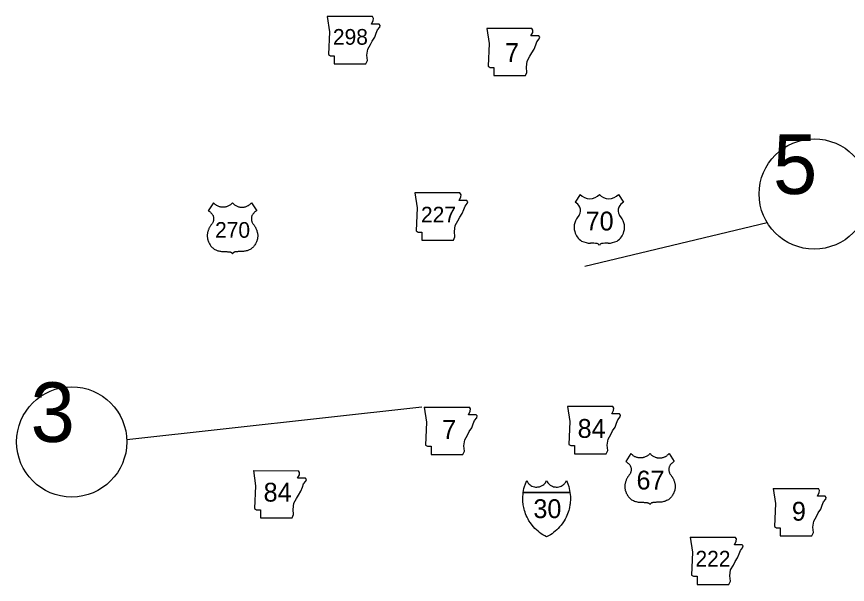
# Model space of a CAD drawing. Extents: x -819161 to 80911, y -6604 to 768454.
# Drawn here: x 40617 to 43414, y -6191 to -4281 of the extents above; entities that cross this region are included whole.
import ezdxf

# ---------------------------------------------------------------- set-up
doc = ezdxf.new("R2010")
doc.units = 0
for name, color, linetype in [('23', 7, 'Continuous'), ('DSN_DRFT_Common-Line', 7, 'Continuous'), ('Level 21', 7, 'Continuous'), ('Level 22', 7, 'Continuous'), ('Level 23', 7, 'Continuous')]:
    doc.layers.add(name, color=color, linetype=linetype)

msp = doc.modelspace()

# ---------------------------------------------------------------- linework, layer by layer
at = {"layer": '23'}
for points in [[(42322.5, -5882.3), (42323.6, -5875), (42325.1, -5868.2), (42326.9, -5861.5), (42329.7, -5853), (42334.3, -5841.8), (42337.8, -5847.7), (42339.4, -5850.2), (42341, -5852.2), (42342.9, -5854), (42345.7, -5856.4), (42348.6, -5858.5), (42351.8, -5860.3), (42355.9, -5861.9), (42360, -5862.8), (42364.3, -5863.4), (42368.9, -5863.6), (42372.2, -5863.3), (42374.9, -5863), (42377.8, -5862.3), (42381.8, -5860.8), (42384.5, -5859.7), (42386.7, -5858.5), (42388.9, -5857.1), (42391.4, -5855.1), (42394.8, -5851.8), (42397.1, -5848.9), (42399.1, -5845.7), (42401.3, -5842)], [(42401.3, -5842), (42403.4, -5845.7), (42405.4, -5848.9), (42407.8, -5851.8), (42411.1, -5855.1), (42413.7, -5857.1), (42415.8, -5858.5), (42418.1, -5859.7), (42420.7, -5860.8), (42424.8, -5862.3), (42427.7, -5863), (42430.4, -5863.3), (42433.7, -5863.6), (42438.3, -5863.4), (42442.6, -5862.8), (42446.6, -5861.9), (42450.7, -5860.3), (42453.9, -5858.5), (42456.8, -5856.4), (42459.6, -5854), (42461.6, -5852.2), (42463.2, -5850.2), (42464.7, -5847.7), (42468.3, -5841.8), (42472.9, -5853), (42475.6, -5861.5), (42477.5, -5868.2), (42478.9, -5875), (42480, -5882.3)], [(42401.3, -6031.3), (42395, -6028), (42388.5, -6024.1), (42382.9, -6020.4), (42377.9, -6016.7), (42372.6, -6012.4), (42366.8, -6007.3), (42362.1, -6002.6), (42357.7, -5997.9), (42352.8, -5992.1), (42346.8, -5984.1), (42342, -5976.7), (42338.9, -5971.3), (42335.9, -5965.4), (42332.8, -5958.8), (42330.5, -5953.1), (42328.6, -5947.8), (42327, -5942.6), (42325.6, -5937.5), (42324.2, -5931.9), (42322.8, -5923.9), (42322.2, -5919.7), (42321.6, -5914), (42321.3, -5907.4), (42321.2, -5901.7), (42321.4, -5895.5), (42321.9, -5888.8), (42322.6, -5882.3)], [(42322.5, -5882.3), (42480, -5882.3)], [(42480, -5882.3), (42322.5, -5882.3)], [(42479.9, -5882.3), (42480.7, -5888.8), (42481.2, -5895.5), (42481.3, -5901.7), (42481.3, -5907.4), (42480.9, -5914), (42480.4, -5919.7), (42479.8, -5923.9), (42478.3, -5931.9), (42477, -5937.5), (42475.6, -5942.6), (42473.9, -5947.8), (42472, -5953.1), (42469.7, -5958.8), (42466.7, -5965.4), (42463.6, -5971.3), (42460.5, -5976.7), (42455.7, -5984.1), (42449.8, -5992.1), (42444.8, -5997.9), (42440.5, -6002.6), (42435.7, -6007.3), (42430, -6012.4), (42424.7, -6016.7), (42419.6, -6020.4), (42414.1, -6024.1), (42407.5, -6028), (42401.3, -6031.3)]]:
    msp.add_lwpolyline(points, dxfattribs=at)
at = {"layer": 'DSN_DRFT_Common-Line'}
msp.add_line((43144.1, -4973.9), (42530, -5121.1), dxfattribs=at)
msp.add_lwpolyline([(40987.4, -5703.1), (41981.2, -5593.9)], dxfattribs=at)
for centre in [(43302.5, -4877.4), (40802.1, -5711.7)]:
    msp.add_circle(centre, 185.5, dxfattribs=at)
at = {"layer": 'Level 21'}
for p, q in [((41989.4, -5594.6), (41997, -5645.3)), ((42145.1, -5600.5), (42141.6, -5594.7)), ((42138.3, -5620), (42144.2, -5608.1)), ((42164.5, -5620), (42138.3, -5620)), ((42144.2, -5608.1), (42145.1, -5600.5)), ((42167.9, -5624.2), (42164.5, -5620)), ((41997, -5645.3), (41993.7, -5722.3)), ((42149.3, -5664), (42154.4, -5650.4)), ((42154.4, -5650.4), (42158.6, -5639.4)), ((42158.6, -5639.4), (42166.2, -5630.1)), ((42166.2, -5630.1), (42167.9, -5624.2)), ((42134.9, -5688.5), (42140.8, -5676.6)), ((42140.8, -5676.6), (42149.3, -5664)), ((42123.1, -5724.9), (42125.6, -5704.6)), ((42125.6, -5704.6), (42134.9, -5688.5)), ((41993.7, -5722.3), (42000.4, -5726.5)), ((42000.4, -5726.5), (42013.1, -5726.5)), ((42013.1, -5726.5), (42013.1, -5753.6)), ((42124.8, -5742.6), (42123.1, -5724.9)), ((42013.1, -5753.6), (42119.7, -5753.6)), ((42119.7, -5753.6), (42124.8, -5742.6)), ((41413.9, -5808.3), (41421.5, -5859.1)), ((41569.6, -5814.2), (41566.1, -5808.4)), ((41568.7, -5821.9), (41569.6, -5814.2)), ((41562.8, -5833.7), (41568.7, -5821.9)), ((41589, -5833.7), (41562.8, -5833.7)), ((41583.1, -5853.2), (41590.7, -5843.9)), ((41592.4, -5837.9), (41589, -5833.7)), ((41590.7, -5843.9), (41592.4, -5837.9)), ((41421.5, -5859.1), (41418.2, -5936.1)), ((41573.8, -5877.7), (41578.9, -5864.2)), ((41578.9, -5864.2), (41583.1, -5853.2)), ((43164.6, -5868.7), (43172.2, -5919.4)), ((43320.2, -5874.6), (43316.7, -5868.7)), ((43319.4, -5882.2), (43320.2, -5874.6)), ((41550.1, -5918.3), (41559.4, -5902.2)), ((41559.4, -5902.2), (41565.3, -5890.4)), ((41565.3, -5890.4), (41573.8, -5877.7)), ((43313.5, -5894.1), (43319.4, -5882.2)), ((43339.7, -5894.1), (43313.5, -5894.1)), ((43343.1, -5898.3), (43339.7, -5894.1)), ((43341.4, -5904.2), (43343.1, -5898.3)), ((41547.6, -5938.6), (41550.1, -5918.3)), ((43172.2, -5919.4), (43168.8, -5996.4)), ((43324.5, -5938), (43329.5, -5924.5)), ((43329.5, -5924.5), (43333.8, -5913.5)), ((43333.8, -5913.5), (43341.4, -5904.2)), ((41418.2, -5936.1), (41424.9, -5940.3)), ((41424.9, -5940.3), (41437.6, -5940.3)), ((41437.6, -5940.3), (41437.6, -5967.4)), ((41544.2, -5967.4), (41549.3, -5956.4)), ((41549.3, -5956.4), (41547.6, -5938.6)), ((43310.1, -5962.6), (43316, -5950.7)), ((43316, -5950.7), (43324.5, -5938)), ((41437.6, -5967.4), (41544.2, -5967.4)), ((43298.2, -5998.9), (43300.8, -5978.6)), ((43300.8, -5978.6), (43310.1, -5962.6)), ((43168.8, -5996.4), (43175.6, -6000.6)), ((43175.6, -6000.6), (43188.3, -6000.6)), ((43188.3, -6000.6), (43188.3, -6027.7)), ((43299.9, -6016.7), (43298.2, -5998.9)), ((42884.6, -6032), (42892.2, -6082.7)), ((43040.3, -6037.9), (43036.8, -6032.1)), ((43039.4, -6045.5), (43040.3, -6037.9)), ((43188.3, -6027.7), (43294.9, -6027.7)), ((43294.9, -6027.7), (43299.9, -6016.7)), ((43033.5, -6057.4), (43039.4, -6045.5)), ((43059.7, -6057.4), (43033.5, -6057.4)), ((43053.8, -6076.8), (43061.4, -6067.5)), ((43063.1, -6061.6), (43059.7, -6057.4)), ((43061.4, -6067.5), (43063.1, -6061.6)), ((42892.2, -6082.7), (42888.9, -6159.7)), ((43044.5, -6101.3), (43049.6, -6087.8)), ((43049.6, -6087.8), (43053.8, -6076.8)), ((43020.8, -6141.9), (43030.1, -6125.9)), ((43030.1, -6125.9), (43036, -6114)), ((43036, -6114), (43044.5, -6101.3)), ((43018.3, -6162.2), (43020.8, -6141.9)), ((42888.9, -6159.7), (42895.6, -6163.9)), ((42895.6, -6163.9), (42908.3, -6163.9)), ((42908.3, -6163.9), (42908.3, -6191)), ((43014.9, -6191), (43020, -6180)), ((43020, -6180), (43018.3, -6162.2)), ((42908.3, -6191), (43014.9, -6191))]:
    msp.add_line(p, q, dxfattribs=at)
for points in [[(41662.6, -4280.6), (41670.2, -4331.3), (41666.8, -4408.3), (41673.6, -4412.5), (41686.3, -4412.5), (41686.3, -4439.6), (41792.9, -4439.6), (41798, -4428.6), (41796.3, -4410.8), (41798.8, -4390.5), (41808.1, -4374.5), (41814, -4362.6), (41822.5, -4349.9), (41827.6, -4336.4), (41831.8, -4325.4), (41839.4, -4316.1), (41841.1, -4310.2), (41837.7, -4305.9), (41811.5, -4305.9), (41817.4, -4294.1), (41818.3, -4286.5), (41814.7, -4280.6)], [(42199.7, -4320.1), (42207.4, -4370.8), (42204, -4447.8), (42210.7, -4452.1), (42223.4, -4452.1), (42223.4, -4479.1), (42330, -4479.1), (42335.1, -4468.1), (42333.4, -4450.4), (42335.9, -4430.1), (42345.2, -4414), (42351.2, -4402.1), (42359.6, -4389.5), (42364.7, -4375.9), (42368.9, -4364.9), (42376.5, -4355.6), (42378.2, -4349.7), (42374.8, -4345.5), (42348.6, -4345.5), (42354.5, -4333.6), (42355.4, -4326), (42351.9, -4320.2)], [(41957.4, -4873.8), (41965, -4924.5), (41961.6, -5001.5), (41968.4, -5005.7), (41981.1, -5005.7), (41981.1, -5032.8), (42087.7, -5032.8), (42092.8, -5021.8), (42091.1, -5004), (42093.6, -4983.7), (42102.9, -4967.7), (42108.8, -4955.8), (42117.3, -4943.1), (42122.4, -4929.6), (42126.6, -4918.6), (42134.2, -4909.3), (42135.9, -4903.4), (42132.5, -4899.2), (42106.3, -4899.2), (42112.2, -4887.3), (42113.1, -4879.7), (42109.6, -4873.9)], [(42471.9, -5592.3), (42479.5, -5643), (42476.1, -5720), (42482.9, -5724.2), (42495.6, -5724.2), (42495.6, -5751.3), (42602.1, -5751.3), (42607.2, -5740.3), (42605.5, -5722.5), (42608.1, -5702.2), (42617.4, -5686.2), (42623.3, -5674.3), (42631.7, -5661.6), (42636.8, -5648.1), (42641.1, -5637.1), (42648.7, -5627.8), (42650.4, -5621.9), (42647, -5617.6), (42620.8, -5617.6), (42626.7, -5605.8), (42627.5, -5598.2), (42624, -5592.3)]]:
    msp.add_lwpolyline(points, close=True, dxfattribs=at)
for points in [[(41989.4, -5594.6), (42141.6, -5594.7)], [(41413.9, -5808.3), (41566.1, -5808.4)], [(43164.6, -5868.7), (43316.7, -5868.7)], [(42884.6, -6032), (43036.8, -6032.1)]]:
    msp.add_lwpolyline(points, dxfattribs=at)
at = {"layer": 'Level 22'}
for p, q in [((42514.5, -4878.6), (42497.2, -4905.4)), ((42643.2, -4878.6), (42660.5, -4905.4))]:
    msp.add_line(p, q, dxfattribs=at)
for points in [[(41343.5, -4907.1), (41342.2, -4908.6), (41340.9, -4909.8), (41339.5, -4911.2), (41338, -4912.5), (41336.5, -4913.7), (41334.7, -4914.9), (41332.7, -4916.1), (41330.5, -4917.3), (41327.7, -4918.6), (41325.6, -4919.5), (41323.1, -4920.3), (41320.9, -4920.8), (41318.9, -4921.3), (41316.7, -4921.6), (41314.7, -4921.8), (41312, -4921.9), (41309.8, -4921.9), (41307.9, -4921.8), (41306, -4921.6), (41304.2, -4921.3), (41301.8, -4920.8), (41299.7, -4920.3), (41297.1, -4919.4), (41294.8, -4918.5), (41292.8, -4917.6), (41290.9, -4916.6), (41289.2, -4915.6), (41287.3, -4914.4), (41285.6, -4913.1), (41284.1, -4911.9), (41282.8, -4910.7), (41281.5, -4909.5), (41280.2, -4908.1), (41279.2, -4906.9), (41261.9, -4933.7), (41263.1, -4934.4), (41264.6, -4935.4), (41266, -4936.4), (41267.8, -4937.8), (41269.3, -4939.1), (41270.6, -4940.4), (41272, -4941.7), (41273.3, -4943.2), (41274.3, -4944.4), (41275.3, -4945.7), (41276.3, -4947.1), (41277.2, -4948.5), (41278.1, -4950.2), (41278.8, -4952.3), (41279.3, -4954.4), (41279.7, -4956.6), (41279.9, -4958.6), (41280, -4960.6), (41279.9, -4962.5), (41279.8, -4963.9), (41279.5, -4965.8), (41279.2, -4967.5), (41278.7, -4969.3), (41278.2, -4971), (41277.5, -4972.8), (41276.4, -4975.2), (41275.2, -4977), (41273.8, -4978.7), (41272.1, -4980.9), (41270.8, -4982.8), (41269.5, -4984.7), (41268.3, -4986.5), (41267.3, -4988.2), (41266.4, -4989.8), (41265.5, -4991.7), (41264.4, -4993.8), (41263.5, -4996), (41262.8, -4997.6), (41262.1, -4999.6), (41261.2, -5002.1), (41260.5, -5004.2), (41259.9, -5006.4), (41259.3, -5009.1), (41258.9, -5011.4), (41258.7, -5013.8), (41258.5, -5016.5), (41258.5, -5019), (41258.6, -5021.4), (41258.9, -5024.3), (41259.4, -5027), (41259.8, -5029.1), (41260.3, -5030.9), (41260.9, -5032.9), (41261.7, -5035.5), (41262.8, -5038.6), (41263.8, -5040.8), (41264.9, -5043.2), (41266.2, -5045.5), (41267.8, -5048.1), (41269.5, -5050.5), (41271.1, -5052.6), (41273, -5054.8), (41275.4, -5057.2), (41277.4, -5059.1), (41279.5, -5060.9)], [(41343.5, -4907.1), (41344.8, -4908.6), (41346.1, -4909.8), (41347.5, -4911.2), (41349.1, -4912.5), (41350.5, -4913.7), (41352.4, -4914.9), (41354.3, -4916.1), (41356.5, -4917.3), (41359.3, -4918.6), (41361.4, -4919.5), (41363.9, -4920.3), (41366.1, -4920.8), (41368.1, -4921.3), (41370.3, -4921.6), (41372.3, -4921.8), (41375, -4921.9), (41377.2, -4921.9), (41379.2, -4921.8), (41381, -4921.6), (41382.8, -4921.3), (41385.2, -4920.8), (41387.3, -4920.3), (41390, -4919.4), (41392.2, -4918.5), (41394.2, -4917.6), (41396.1, -4916.6), (41397.8, -4915.6), (41399.7, -4914.4), (41401.5, -4913.1), (41403, -4911.9), (41404.2, -4910.7), (41405.5, -4909.5), (41406.8, -4908.1), (41407.9, -4906.9), (41425.2, -4933.7), (41423.9, -4934.4), (41422.5, -4935.4), (41421.1, -4936.4), (41419.2, -4937.8), (41417.7, -4939.1), (41416.4, -4940.4), (41415.1, -4941.7), (41413.7, -4943.2), (41412.7, -4944.4), (41411.7, -4945.7), (41410.7, -4947.1), (41409.8, -4948.5), (41408.9, -4950.2), (41408.2, -4952.3), (41407.7, -4954.4), (41407.3, -4956.6), (41407.1, -4958.6), (41407.1, -4960.6), (41407.1, -4962.5), (41407.2, -4963.9), (41407.5, -4965.8), (41407.8, -4967.5), (41408.3, -4969.3), (41408.8, -4971), (41409.5, -4972.8), (41410.7, -4975.2), (41411.8, -4977), (41413.2, -4978.7), (41414.9, -4980.9), (41416.3, -4982.8), (41417.6, -4984.7), (41418.7, -4986.5), (41419.7, -4988.2), (41420.6, -4989.8), (41421.6, -4991.7), (41422.6, -4993.8), (41423.6, -4996), (41424.2, -4997.6), (41425, -4999.6), (41425.8, -5002.1), (41426.5, -5004.2), (41427.1, -5006.4), (41427.7, -5009.1), (41428.1, -5011.4), (41428.4, -5013.8), (41428.5, -5016.5), (41428.5, -5019), (41428.4, -5021.4), (41428.1, -5024.3), (41427.7, -5027), (41427.2, -5029.1), (41426.7, -5030.9), (41426.2, -5032.9), (41425.4, -5035.5), (41424.2, -5038.6), (41423.2, -5040.8), (41422.1, -5043.2), (41420.8, -5045.5), (41419.2, -5048.1), (41417.5, -5050.5), (41415.9, -5052.6), (41414, -5054.8), (41411.6, -5057.2), (41409.6, -5059.1), (41407.5, -5060.9)], [(41279.5, -5060.9), (41281.7, -5062.5), (41284.3, -5064.2), (41287.6, -5065.7), (41291.4, -5067.2), (41294.5, -5068.2), (41297.3, -5069), (41300.5, -5069.7), (41303.5, -5070.2), (41306.7, -5070.7), (41310.8, -5071), (41313.9, -5071.1), (41316.5, -5071.1), (41319.1, -5071.2), (41321.7, -5071.2), (41324.1, -5071.4), (41326.2, -5071.5), (41328.3, -5071.7), (41331, -5072), (41333.7, -5072.3), (41335.2, -5072.5), (41336.5, -5072.8), (41338.1, -5073.4), (41339, -5073.9), (41339.8, -5074.4), (41340.9, -5075.3), (41341.9, -5076.3), (41342.7, -5077.4), (41343.5, -5078.7)], [(41407.5, -5060.9), (41405.4, -5062.5), (41402.7, -5064.2), (41399.5, -5065.7), (41395.6, -5067.2), (41392.5, -5068.2), (41389.7, -5069), (41386.5, -5069.7), (41383.5, -5070.2), (41380.3, -5070.7), (41376.3, -5071), (41373.2, -5071.1), (41370.5, -5071.1), (41367.9, -5071.2), (41365.4, -5071.2), (41362.9, -5071.4), (41360.8, -5071.5), (41358.7, -5071.7), (41356, -5072), (41353.4, -5072.3), (41351.8, -5072.5), (41350.5, -5072.8), (41348.9, -5073.4), (41348, -5073.9), (41347.2, -5074.4), (41346.1, -5075.3), (41345.1, -5076.3), (41344.3, -5077.4), (41343.5, -5078.7)], [(42749.4, -5750.7), (42748.1, -5752.2), (42746.9, -5753.5), (42745.4, -5754.8), (42743.9, -5756.2), (42742.4, -5757.3), (42740.6, -5758.6), (42738.7, -5759.8), (42736.5, -5761), (42733.7, -5762.3), (42731.5, -5763.1), (42729.1, -5763.9), (42726.9, -5764.5), (42724.8, -5764.9), (42722.6, -5765.3), (42720.7, -5765.5), (42717.9, -5765.6), (42715.7, -5765.6), (42713.8, -5765.4), (42712, -5765.3), (42710.1, -5765), (42707.8, -5764.5), (42705.6, -5763.9), (42703, -5763.1), (42700.8, -5762.2), (42698.7, -5761.3), (42696.9, -5760.3), (42695.2, -5759.3), (42693.2, -5758), (42691.5, -5756.7), (42690, -5755.5), (42688.7, -5754.4), (42687.4, -5753.1), (42686.1, -5751.8), (42685.1, -5750.6), (42667.8, -5777.4), (42669, -5778.1), (42670.5, -5779.1), (42671.9, -5780), (42673.7, -5781.5), (42675.2, -5782.8), (42676.6, -5784), (42677.9, -5785.4), (42679.3, -5786.9), (42680.2, -5788.1), (42681.2, -5789.3), (42682.2, -5790.7), (42683.2, -5792.2), (42684.1, -5793.9), (42684.7, -5795.9), (42685.2, -5798), (42685.6, -5800.2), (42685.8, -5802.3), (42685.9, -5804.3), (42685.8, -5806.1), (42685.7, -5807.6), (42685.5, -5809.4), (42685.1, -5811.1), (42684.7, -5813), (42684.1, -5814.6), (42683.4, -5816.4), (42682.3, -5818.8), (42681.1, -5820.7), (42679.7, -5822.3), (42678.1, -5824.5), (42676.7, -5826.4), (42675.4, -5828.3), (42674.2, -5830.2), (42673.2, -5831.9), (42672.4, -5833.4), (42671.4, -5835.3), (42670.3, -5837.5), (42669.4, -5839.6), (42668.8, -5841.2), (42668, -5843.3), (42667.1, -5845.7), (42666.5, -5847.8), (42665.8, -5850.1), (42665.3, -5852.7), (42664.9, -5855), (42664.6, -5857.5), (42664.4, -5860.2), (42664.4, -5862.6), (42664.5, -5865.1), (42664.8, -5868), (42665.3, -5870.7), (42665.7, -5872.8), (42666.2, -5874.6), (42666.8, -5876.6), (42667.6, -5879.1), (42668.7, -5882.2), (42669.7, -5884.5), (42670.9, -5886.8), (42672.1, -5889.1), (42673.7, -5891.7), (42675.4, -5894.2), (42677.1, -5896.3), (42678.9, -5898.4), (42681.3, -5900.9), (42683.3, -5902.8), (42685.4, -5904.5)], [(42749.4, -5750.7), (42750.8, -5752.2), (42752, -5753.5), (42753.4, -5754.8), (42755, -5756.2), (42756.5, -5757.3), (42758.3, -5758.6), (42760.2, -5759.8), (42762.4, -5761), (42765.2, -5762.3), (42767.4, -5763.1), (42769.8, -5763.9), (42772, -5764.5), (42774.1, -5764.9), (42776.2, -5765.3), (42778.2, -5765.5), (42780.9, -5765.6), (42783.2, -5765.6), (42785.1, -5765.4), (42786.9, -5765.3), (42788.8, -5765), (42791.1, -5764.5), (42793.3, -5763.9), (42795.9, -5763.1), (42798.1, -5762.2), (42800.1, -5761.3), (42802, -5760.3), (42803.7, -5759.3), (42805.6, -5758), (42807.4, -5756.7), (42808.9, -5755.5), (42810.2, -5754.4), (42811.5, -5753.1), (42812.8, -5751.8), (42813.8, -5750.6), (42831.1, -5777.4), (42829.9, -5778.1), (42828.4, -5779.1), (42827, -5780), (42825.1, -5781.5), (42823.6, -5782.8), (42822.3, -5784), (42821, -5785.4), (42819.6, -5786.9), (42818.6, -5788.1), (42817.7, -5789.3), (42816.7, -5790.7), (42815.7, -5792.2), (42814.8, -5793.9), (42814.2, -5795.9), (42813.6, -5798), (42813.3, -5800.2), (42813.1, -5802.3), (42813, -5804.3), (42813, -5806.1), (42813.2, -5807.6), (42813.4, -5809.4), (42813.7, -5811.1), (42814.2, -5813), (42814.7, -5814.6), (42815.5, -5816.4), (42816.6, -5818.8), (42817.7, -5820.7), (42819.1, -5822.3), (42820.8, -5824.5), (42822.2, -5826.4), (42823.5, -5828.3), (42824.7, -5830.2), (42825.6, -5831.9), (42826.5, -5833.4), (42827.5, -5835.3), (42828.5, -5837.5), (42829.5, -5839.6), (42830.1, -5841.2), (42830.9, -5843.3), (42831.7, -5845.7), (42832.4, -5847.8), (42833, -5850.1), (42833.6, -5852.7), (42834, -5855), (42834.3, -5857.5), (42834.4, -5860.2), (42834.5, -5862.6), (42834.3, -5865.1), (42834, -5868), (42833.6, -5870.7), (42833.1, -5872.8), (42832.7, -5874.6), (42832.1, -5876.6), (42831.3, -5879.1), (42830.1, -5882.2), (42829.2, -5884.5), (42828, -5886.8), (42826.8, -5889.1), (42825.1, -5891.7), (42823.5, -5894.2), (42821.8, -5896.3), (42820, -5898.4), (42817.6, -5900.9), (42815.5, -5902.8), (42813.5, -5904.5)], [(42685.4, -5904.5), (42687.6, -5906.2), (42690.2, -5907.9), (42693.5, -5909.3), (42697.3, -5910.8), (42700.4, -5911.8), (42703.3, -5912.6), (42706.4, -5913.3), (42709.4, -5913.9), (42712.6, -5914.3), (42716.7, -5914.7), (42719.8, -5914.8), (42722.4, -5914.8), (42725, -5914.8), (42727.6, -5914.9), (42730, -5915), (42732.2, -5915.2), (42734.3, -5915.3), (42737, -5915.6), (42739.6, -5915.9), (42741.2, -5916.2), (42742.5, -5916.4), (42744, -5917.1), (42744.9, -5917.6), (42745.7, -5918.1), (42746.8, -5919), (42747.8, -5920), (42748.7, -5921.1), (42749.4, -5922.3)], [(42813.5, -5904.5), (42811.3, -5906.2), (42808.7, -5907.9), (42805.4, -5909.3), (42801.6, -5910.8), (42798.4, -5911.8), (42795.6, -5912.6), (42792.4, -5913.3), (42789.5, -5913.9), (42786.2, -5914.3), (42782.2, -5914.7), (42779.1, -5914.8), (42776.5, -5914.8), (42773.9, -5914.8), (42771.3, -5914.9), (42768.9, -5915), (42766.7, -5915.2), (42764.6, -5915.3), (42761.9, -5915.6), (42759.3, -5915.9), (42757.7, -5916.2), (42756.4, -5916.4), (42754.8, -5917.1), (42753.9, -5917.6), (42753.2, -5918.1), (42752.1, -5919), (42751, -5920), (42750.2, -5921.1), (42749.4, -5922.3)]]:
    msp.add_lwpolyline(points, dxfattribs=at)
for centre, radius, start, end in [((42546.8, -4851.5), 42.1, 220.075, 319.6701), ((42611, -4851.5), 42.1, 220.3299, 319.925), ((42474.6, -4944.2), 45, 30.7809, 59.9883), ((42484.5, -4932.4), 30.8, 328.8105, 21.2108), ((42673.2, -4932.4), 30.8, 158.7892, 211.1895), ((42683.1, -4944.2), 45, 120.0117, 149.2191), ((42565.1, -4995.6), 71.9, 138.9565, 162.6913), ((42592.6, -4995.6), 71.9, 17.3087, 41.0435), ((42541.4, -4989.7), 47.5, 160.9576, 197.3819), ((42616.4, -4989.7), 47.5, 342.6181, 19.0424), ((42549.1, -4989.5), 55, 195.1074, 237.1312), ((42608.6, -4989.5), 55, 302.8688, 344.8926), ((42550.1, -4972.2), 70.6, 244.0771, 269.5779), ((42551.8, -5172.1), 129.3, 81.1942, 90.9539), ((42567.9, -5056.2), 12.4, 28.0342, 72.9864), ((42589.8, -5056.2), 12.4, 107.0136, 151.9658), ((42606, -5172.1), 129.3, 89.0461, 98.8058), ((42607.6, -4972.2), 70.6, 270.4221, 295.9229)]:
    msp.add_arc(centre, radius, start, end, dxfattribs=at)

# ---------------------------------------------------------------- texts
at = {"layer": 'DSN_DRFT_Common-Line'}
for s, p in [('5', (43163.6, -4877.4)), ('3', (40663.6, -5711.7))]:
    msp.add_text(s, height=200.4, dxfattribs=at).set_placement(p)
at = {"layer": 'Level 21'}
for s, height, p in [('298', 52.8, (41681.7, -4375.1)), ('7', 63.4, (42261.4, -4433.2)), ('227', 52.8, (41978.3, -4973.2)), ('7', 63.4, (42049.4, -5701.3)), ('84', 63.36, (42505.8, -5698)), ('84', 63.36, (41448.3, -5912.5)), ('9', 63.4, (43227.3, -5976.7)), ('222', 52.8, (42902.6, -6131))]:
    msp.add_text(s, height=height, dxfattribs=at).set_placement(p)
at = {"layer": 'Level 22'}
for s, height, p in [('70', 63.36, (42532.7, -5000.1)), ('270', 52.8, (41284.9, -5024.7)), ('67', 63.36, (42704.1, -5871.8))]:
    msp.add_text(s, height=height, dxfattribs=at).set_placement(p)
at = {"layer": 'Level 23'}
msp.add_text('30', height=63.36, dxfattribs=at).set_placement((42356.9, -5968))

doc.saveas('drawing.dxf')
